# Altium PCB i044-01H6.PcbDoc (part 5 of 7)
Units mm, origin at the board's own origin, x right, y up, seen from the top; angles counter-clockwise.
Board outline 42 x 29.01 mm, 8 copper layers (Top Layer, Mid-Layer 1, Mid-Layer 2, Mid-Layer 3, Mid-Layer 4, Mid-Layer 5, Mid-Layer 6, Bottom Layer), stack 1.474 mm thick; 235 components, 197 nets, 1006 pads, 1183 vias.
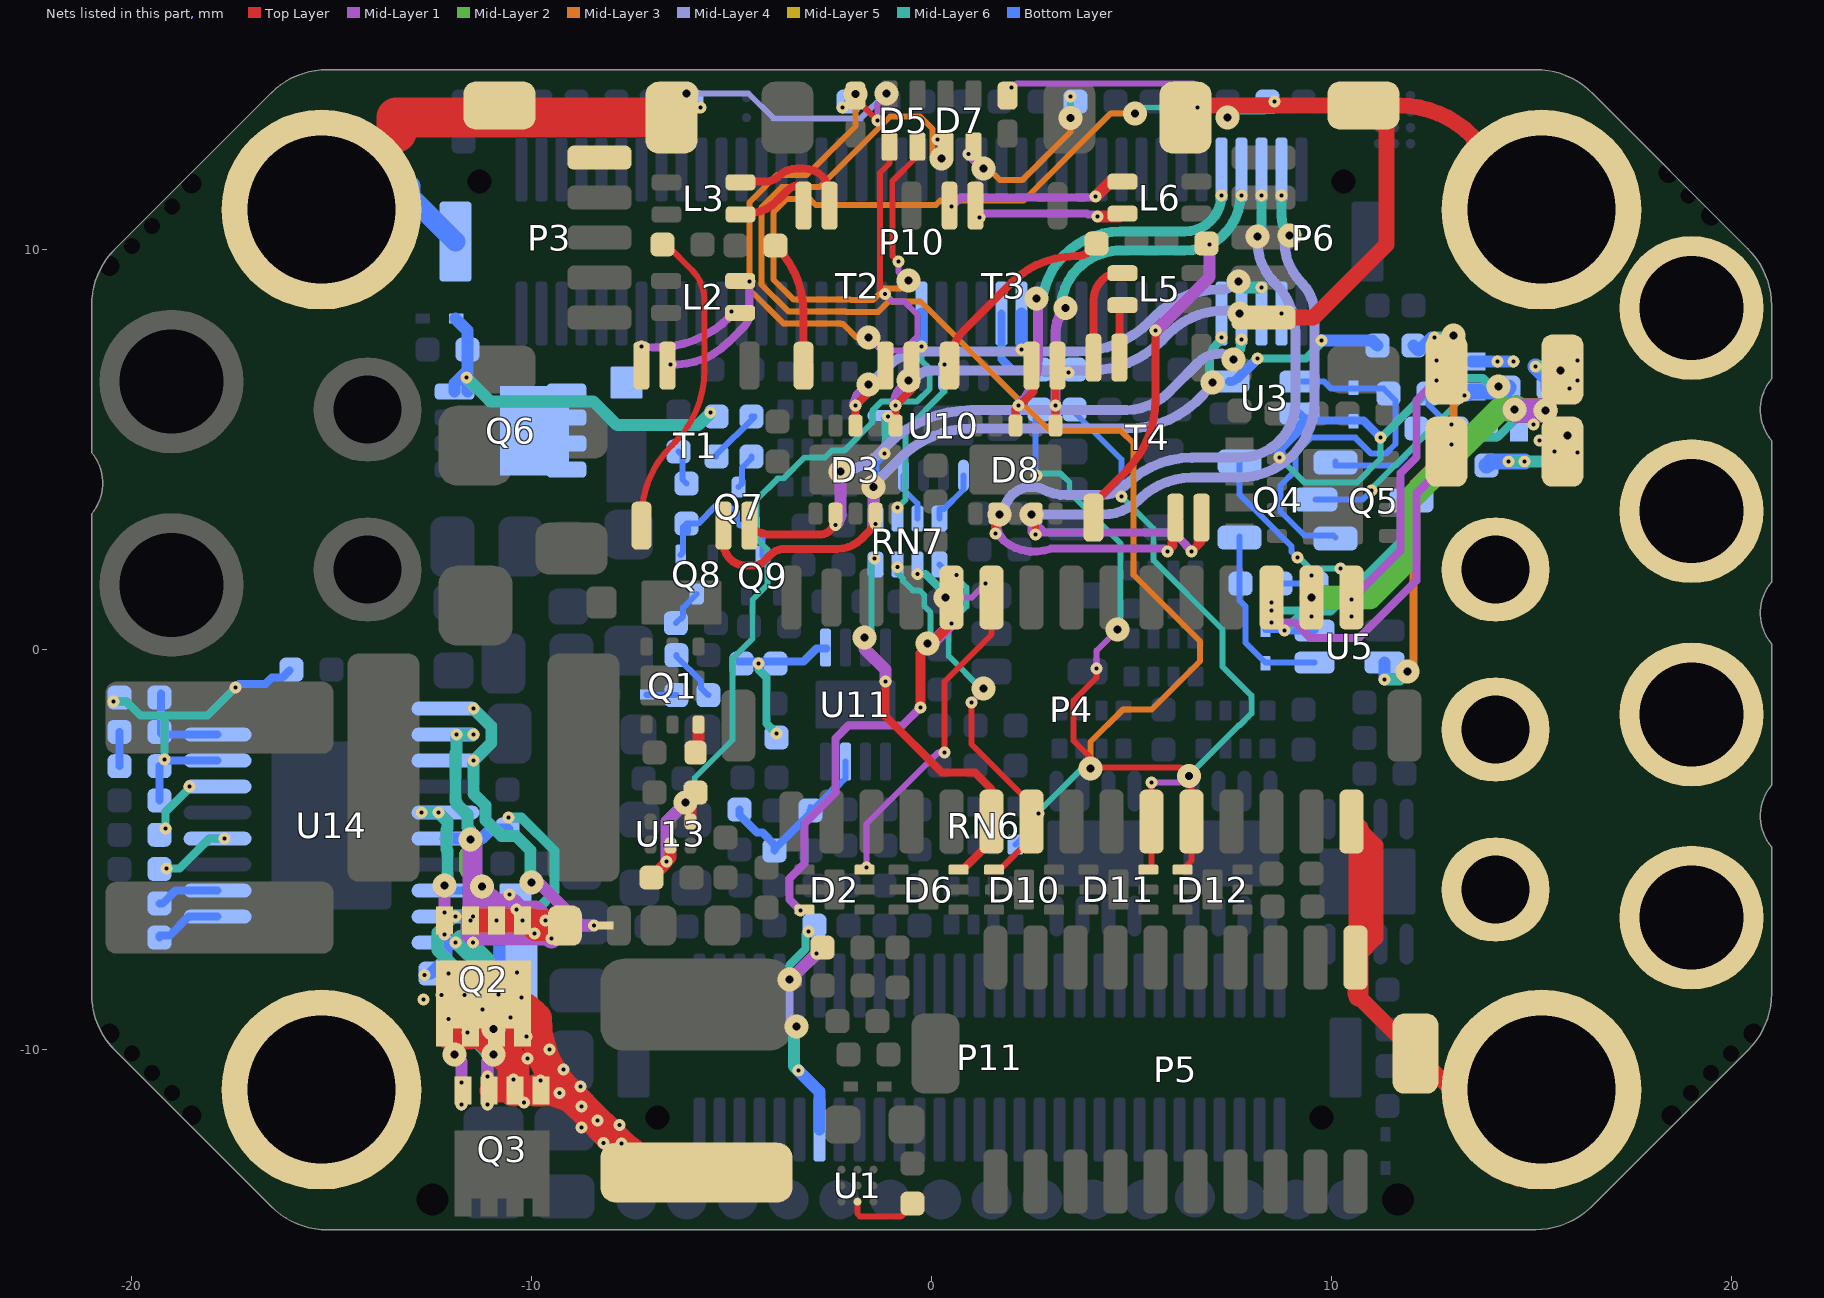
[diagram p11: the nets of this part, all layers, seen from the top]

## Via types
v1: diameter 0.3/0.3 (per signal layer), hole 0.1, Mid-Layer 6 to Bottom Layer, 515 vias
v2: diameter 0.3/0.3 (per signal layer), hole 0.1, Top Layer to Mid-Layer 1, 392 vias
v3: diameter 0.6, hole 0.2, Mid-Layer 1 to Mid-Layer 6, 276 vias

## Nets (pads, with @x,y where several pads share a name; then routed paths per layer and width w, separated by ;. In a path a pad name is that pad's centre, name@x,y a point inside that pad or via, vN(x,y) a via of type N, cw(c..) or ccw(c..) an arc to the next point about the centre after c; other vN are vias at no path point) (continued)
NetC33_1: C33.1 R35.1 R37.2 U11.3 | length 4.6
  Bottom Layer w0.15: C33.1@-3.025,-3.938 C33.1@-3.025,-4.025 C33.1@-3.01,-4.025 ; C33.1@-3.011,-4.026 C33.1@-3.01,-4.025 ; C33.1@-3.005,-4.025 C33.1@-3.01,-4.025 ; -2.433,-3.475 -2.408,-3.475 U11.3@-2.15,-3.217 ; -2.416,-3.488 -2.469,-3.489 C33.1@-3.01,-4.025 ; U11.3@-2.15,-3.192 U11.3@-2.15,-2.8
  Bottom Layer w0.2: R35.1@-4.8,-4 -4.8,-4.134 -4.359,-4.575 -4.226,-4.575 -3.925,-4.876 R37.2@-3.925,-4.989 ; R37.2@-3.925,-5.025 R37.2@-3.925,-4.989 ; R37.2@-3.925,-4.925 R37.2@-3.925,-4.989 ; C33.1@-3.025,-4.025 -3.025,-4.089 R37.2@-3.925,-4.989
NetC34_2: C34.2 R36.1 R38.1 U11.5 | length 4.3
  Mid-Layer 6 w0.2: v1(-4.325,-0.35) -4.325,-0.5 -4.125,-0.7 -4.125,-1.85 v1(-3.875,-2.1)
  Bottom Layer w0.2: R38.1@-4.825,-0.3 -3.2,-0.3 -2.875,0.025 U11.5@-2.627,0.025
NetC40_1: C40.1 U14.5 | length 1.8
  Mid-Layer 6 w0.2: v1(-19.125,-5.475) -18.8,-5.475 -18.05,-4.725 v1(-17.675,-4.725)
NetC41_2: C41.2 U14.2 | length 1.7
  Bottom Layer w0.2: C41.2@-19.3,-7.2 -19.3,-7.143 -19.043,-7.143 -18.575,-6.675 U14.2@-17.85,-6.675
NetC44_1: C44.1 L1.1 Q2.5 Q2.6 Q2.7 Q2.8 Q2.9 Q3.1 Q3.2 Q3.3 U14.20 | length 22.5
  Top Layer w0.6: Q2.5@-12.075,-9.7 Q2.6@-11.525,-9.7 ; Q3.3@-11,-11.025 -10.45,-11.025 Q3.1@-9.9,-11.025 ; Q2.7@-10.875,-9.7 Q2.8@-10.325,-9.7
  Top Layer w0.8: Q3.2@-10.45,-11.025 v2(-10.45,-10.75) -10.45,-10.343 -11.2,-9.593 Q2.9@-11.2,-8.625 cw(c-11.2,-10.333) -9.992,-9.125 -9.891,-9.226 ccw(c-7.351,-9.226) -9.147,-11.023 v2@-8.825,-11.345 ; Q3.1@-9.9,-11.025 -9.8,-11.025 -9.597,-11.025 cw(c-9.597,-12.116) v2@-8.825,-11.345 ; L1.1@-5.875,-13.075 -6.043,-13.075 cw(c-6.043,-10.535) -7.839,-12.331 v2(-8.745,-11.425) v2@-8.825,-11.345
  Mid-Layer 1 w0.3: v2(-11.104,-11.366) v2(-11.104,-10.675) -11.104,-10.279 v3(-10.95,-10.125)
  Mid-Layer 2 w0.3: v3(-10.95,-10.125) v3(-10.95,-9.487)
  Mid-Layer 3 w0.3: v3(-10.95,-10.125) v3(-10.95,-9.487)
  Mid-Layer 4 w0.3: v3(-10.95,-10.125) v3(-10.95,-9.487)
  Mid-Layer 5 w0.3: v3(-10.95,-10.125) v3(-10.95,-9.487)
  Mid-Layer 6 w0.6: -11.72,-7.293 -11.225,-7.788 -11.225,-9.212 ; v3(-10.95,-10.125) v3@-10.95,-10.039 ; -11.225,-9.212 -11.226,-9.214 -11.226,-9.763 v3@-10.95,-10.039 ; -11.225,-9.212 v3(-10.95,-9.487) v3@-10.95,-10.039
  Bottom Layer w0.3: C44.1@-12.525,-8.1 -12.125,-7.7 U14.20@-12.125,-7.325
  other v1: -11.9,-7.325 -11.467,-7.325
  other v2: -7.75,-12.35 -8.197,-12.331 -8.75,-11.941 -7.8,-11.885 -8.35,-11.775 -10.191,-11.325 -9.3,-11.082 -8.775,-10.925 -9.775,-10.775 -9.2,-10.5 -10.1,-10.225 -9.546,-10.001 -10.125,-9.675 -11.6,-9.574 -12.079,-9.23 -10.525,-9.2 -11.225,-9 -12.7,-8.75 -10.251,-8.7 -12.25,-8.635 -11.675,-8.635 -10.826,-8.625 -12.675,-8.133 -11.25,-8.133 -12.075,-8.1 -10.366,-8.075
NetC44_2: C44.2 D19.2 U14.18 | length 4.4
  Bottom Layer w0.2: U14.18@-12.15,-6.025 -11.478,-6.025 -11.05,-6.453 -11.05,-6.912 ; C44.2@-11.6,-8.1 C44.2@-11.525,-8.1 ; D19.2@-10.851,-7.799 -10.55,-8.1 D19.2@-10.4,-8.25
  Bottom Layer w0.3: C44.2@-11.525,-8.1 D19.2@-10.55,-8.1 ; -11.05,-6.912 -10.8,-7.162 D19.2@-10.8,-7.799
NetC45_2: C45.2 U14.7 | length 1.3
  Mid-Layer 6 w0.2: v1(-19.15,-4.475) -19.15,-4.06 -18.55,-3.46 v1(-18.55,-3.425)
NetC47_1: C47.1 R44.1 R45.2 R46.2 U14.8 | length 8.3
  Mid-Layer 6 w0.2: v1(-20.45,-1.3) -20.126,-1.3 -19.776,-1.65 -19.15,-1.65 ; v1(-19.175,-2.75) -19.175,-1.675 -19.15,-1.65 ; v1(-17.4,-0.95) -18.1,-1.65 -19.15,-1.65
  Bottom Layer w0.2: R44.1@-19.3,-3.771 R46.2@-19.3,-2.914 ; R46.2@-19.161,-2.775 U14.8@-17.85,-2.775 ; v1(-17.4,-0.95) -17.311,-0.861 -16.651,-0.861 -16.49,-0.7 -16.225,-0.7 R45.2@-16.05,-0.525
NetC47_2: C47.2 C51.2 U14.9 | length 2.4
  Bottom Layer w0.2: C47.2@-19.258,-1.1 -19.258,-2.1 -19.232,-2.125 U14.9@-17.85,-2.125
NetC49_2: C49.2 D19.1 U14.16 | length 5.7
  Mid-Layer 6 w0.25: v1(-10.575,-4.2) -10.248,-4.2 -9.425,-5.023 -9.425,-6.062 -9.864,-6.5 v1(-10.375,-6.5) -10.547,-6.328 v1(-10.547,-6.125)
  Bottom Layer w0.3: U14.16@-12.15,-4.725 -11.25,-4.725 -11.025,-4.5 C49.2@-10.6,-4.5
NetC51_1: C51.1 R46.1 | length 0.9
  Bottom Layer w0.2: R46.1@-20.3,-2.914 C51.1@-20.3,-2.057
NetD4_2: D4.2 R29.1 | length 8.1
  Top Layer w0.15: D4.2@-1.9,13.85 -1.9,13.745 -1.87,13.745 v2(-1.35,13.225)
  Mid-Layer 1 w0.15: v2(-1.35,13.225) -1.35,13.65 -1.148,13.852 v3@-1.148,13.9
  Mid-Layer 4 w0.15: v3(-6.13,13.905) -4.575,13.905 -3.95,13.28 -1.768,13.28 v3@-1.148,13.9
  Mid-Layer 6 w0.15: v3(-6.13,13.905) v1(-5.775,13.55)
  Bottom Layer w0.15: R29.1@-6,13.7 -6,13.5 -5.825,13.5 v1(-5.775,13.55)
  other v3: -1.123,13.9
NetD5_1: D5.1 R31.2 | length 17.3
  Top Layer w0.15: v2(-1.16,8.885) -1.294,9.019 -1.294,11.916 -1.05,12.16 D5.1@-1.05,12.575
  Mid-Layer 1 w0.15: v3(-1.575,7.8) -1.25,7.475 -0.715,7.475 -0.35,7.84 -0.35,8.367 -0.688,8.705 -0.98,8.705 v2(-1.16,8.885)
  Mid-Layer 3 w0.15: v3@-1.921,13.895 v3(-1.9,13.895) -1.9,13.088 -3.123,11.865 -3.866,11.865 -4.55,11.181 -4.55,9.002 -3.703,8.155 -2.281,8.155 -2.267,8.141 -2.209,8.141 -1.868,7.8 v3(-1.575,7.8)
  Mid-Layer 6 w0.15: v1(-2.225,13.55) -2.225,13.57 v3(-1.9,13.895)
NetD5_2: D5.2 R25.2 | length 21.1
  Top Layer w0.15: v2(-0.825,9.7) -0.97,9.845 -0.97,11.721 -0.35,12.341 D5.2@-0.35,12.575
  Mid-Layer 1 w0.15: v2(-0.825,9.7) -0.825,9.435 v3@-0.59,9.2
  Mid-Layer 3 w0.15: v3@-0.57,9.23 -0.775,9.025 -1.175,9.025 -1.459,8.741 -2.018,8.741 -2.032,8.755 -3.454,8.755 -3.95,9.251 -3.95,10.932 -3.617,11.265 -3.04,11.265 -2.89,11.115 0.108,11.115 0.218,11.225 2.3,11.225 4.485,13.41 v3(5.083,13.41)
  Mid-Layer 6 w0.15: v3(5.083,13.41) 5.224,13.55 v1(6.65,13.55)
  other v3: -0.58,9.23
NetD7_1: D7.1 RN6.1 | length 33.7
  Top Layer w0.15: v2(0.15,12.75) 0.18,12.75 0.205,12.775 0.265,12.715 0.265,12.54 D7.1@0.35,12.54
  Mid-Layer 1 w0.15: v2(0.15,12.75) 0.25,12.65 v3(0.25,12.275)
  Mid-Layer 3 w0.15: v3(0.25,12.275) 0.25,12.108 0.025,12.333 0.025,13.017 -0.283,13.325 -1.037,13.325 -2.797,11.565 -3.742,11.565 -4.25,11.057 -4.25,9.126 -3.579,8.455 -2.156,8.455 -2.142,8.441 -1.335,8.441 -1.071,8.705 -0.627,8.705 -0.276,8.705 2.954,5.475 4.731,5.475 5.05,5.156 5.05,1.867 6.715,0.202 6.715,-0.285 5.5,-1.5 4.783,-1.5 3.975,-2.308 v3(3.975,-2.975)
  Mid-Layer 6 w0.15: v1(2.675,-4.1) 2.675,-4.058 3.758,-2.975 v3(3.975,-2.975)
  Bottom Layer w0.15: RN6.1@2.1,-4.875 2.675,-4.3 v1(2.675,-4.1)
NetD7_2: D7.2 R27.2 | length 4.5
  Top Layer w0.15: D7.2@1.05,12.54 D7.2@1.05,12.575
  Mid-Layer 1 w0.25: v2(0.93,12.395) v3(1.3,12.025)
  Mid-Layer 3 w0.15: v3@1.26,12.24 v3@1.45,12.05 ; v3(1.3,12.025) 1.422,12.025 1.711,11.736 2.267,11.736 3.47,12.938 v3(3.47,13.29)
  Mid-Layer 6 w0.15: v3(3.47,13.29) 3.475,13.295 v1(3.475,13.825)
NetD9_2: D9.2 R22.1 | length 7.1
  Mid-Layer 1 w0.15: v2@2,14.025 2.125,14.15 6.55,14.15 v3(7.4,13.3)
  Mid-Layer 6 w0.15: v3(7.4,13.3) 7.55,13.45 8.325,13.45 v1(8.575,13.7)
  other v2: 2,14.05
NetD15_1: D15.1 Q4.3 R55.1 | length 6
  Mid-Layer 6 w0.15: v1(11,3.975) 11,4.025 v1(13.325,6.35)
  Bottom Layer w0.15: Q4.3@9.6,3.75 10.775,3.75 v1(11,3.975)
  Bottom Layer w0.3: v1(13.325,6.35) 13.4,6.35 D15.1@13.5,6.45
  Bottom Layer w0.4: D15.1@13.5,6.45 14.325,6.45 R55.1@14.425,6.55
NetD16_1: D16.1 Q6.4 R2.2 R58.2 | length 9.3
  Mid-Layer 6 w0.3: v1(-11.625,6.8) -11.033,6.208 -8.459,6.208 -7.867,5.615 -5.835,5.615 v1(-5.525,5.925)
  Bottom Layer w0.3: Q6.4@-11.925,6.45 -11.925,6.65 -11.6,6.975 ; D16.1@-11.9,8.275 -11.6,7.975 R58.2@-11.6,7.5 -11.6,6.975 ; Q6.4@-11.6,6.457 -11.6,6.975
NetD17_1: D17.1 R49.1 | length 0.8
  Bottom Layer w0.15: D17.1@-7.13,-1.12 -7.12,-1.13 -6.39,-1.13 R49.1@-6.38,-1.14
NetD21_1: D21.1 Q6.5 Q6.6 Q6.7 Q6.8 Q6.9
NetD22_1: D22.1 Q5.3 R56.1 | length 2.8
  Bottom Layer w0.15: R56.1@12.875,4.6 13.03,4.6 D22.1@13.962,5.531
  Bottom Layer w0.4: Q5.3@12,3.725 12.062,3.725 12.409,4.072 12.409,4.127 12.464,4.127 12.875,4.538 R56.1@12.875,4.6
NetD23_2: D23.2 Q4.1 R51.2 U5.1 | length 4.6
  Bottom Layer w0.15: Q4.1@7.7,2.825 7.7,1.232 7.849,1.083 7.849,0.176 8.35,-0.325 U5.1@9.575,-0.325
NetD24_2: D24.2 Q5.1 R53.2 U3.1 | length 9.9
  Bottom Layer w0.15: U3.1@9.2,6.7 9.814,6.7 9.989,6.525 10.55,6.525 11.3,6.525 R53.2@11.425,6.4 11.6,6.225 11.6,5.14 11.36,4.9 10.995,4.9 10.595,5.3 9.48,5.3 9.102,4.921 9.102,4.484 8.725,4.107 8.725,3.453 9.325,2.853 10.047,2.853 Q5.1@10.1,2.8
NetL2_3: L2.3 T1.4 | length 2.6
  Mid-Layer 1 w0.2: v2(-7.25,7.575) ccw(c-6.907,10.206) -5.03,8.329 ccw(c-5.101,8.4) -5,8.4 v2(-5,8.45)
NetL2_4: L2.4 T1.5 | length 3.4
  Mid-Layer 1 w0.2: v2@-6.597,7.137 ccw(c-6.421,9.029) -5.077,7.686 -4.691,8.072 ccw(c-5.031,8.412) -4.55,8.412 v2(-4.55,9.2) cw(c-4.61,9.14) v2@-4.525,9.14
  other v2: -6.525,7.125
NetL3_3: L3.3 T2.4 | length 1.9
  Top Layer w0.2: L3.3@-4.775,10.9 -4.635,10.9 ccw(c-4.635,12.01) -3.85,11.225 -3.6,11.475 cw(c-3.338,11.262) T2.4@-3.125,11.525
NetL3_4: L3.4 T2.5 | length 3
  Top Layer w0.2: L3.4@-4.775,11.7 -4.162,11.7 ccw(c-4.162,12.212) -3.8,11.85 cw(c-3.378,11.428) -3.378,12.025 -3.188,12.025 cw(c-3.188,11.387) -2.55,11.387 T2.5@-2.55,11.1
NetL5_3: L5.3 T4.4 | length 2.6
  Top Layer w0.2: T4.4@4.05,7.3 4.05,8.725 cw(c4.775,8.725) L5.3@4.775,9.45
NetL5_4: L5.4 T4.5 | length 1.4
  Top Layer w0.2: T4.5@4.7,7.3 4.7,8.65 L5.4@4.775,8.65
NetL6_3: L6.3 T3.4 | length 4.5
  Top Layer w0.3: v2(4.1,11.325) 4.475,11.7 L6.3@4.775,11.7
  Mid-Layer 1 w0.2: v2(0.5,11.075) 0.725,11.3 4.075,11.3 v2(4.1,11.325)
NetL6_4: L6.4 T3.5 | length 3.6
  Top Layer w0.3: v2(4.15,10.825) L6.4@4.7,10.825
  Mid-Layer 1 w0.2: v2(1.2,10.8) 1.3,10.9 3.889,10.9 3.914,10.875 4.15,10.875 v2(4.15,10.825)
NetNT1_1: NT1.1 U14.11 U14.13 | length 7.6
  Mid-Layer 1 w0.3: v3(-10,-5.823) -9.824,-5.823 -8.747,-6.9 v2@-8.5,-6.9
  Mid-Layer 6 w0.3: v1(-11.45,-1.475) -11,-1.925 -11,-2.325 v1(-11.45,-2.775) -11.45,-3.599 -11.156,-3.893 -11.156,-4.255 -10.747,-4.664 -10.385,-4.664 -10.03,-5.019 -10.03,-5.334 -10.025,-5.339 -10.025,-5.875 -10,-5.85 v3(-10,-5.823)
  other v2: -8.442,-6.899
NetQ1_3: Q1.3 R42.2 | length 0.7
  Top Layer w0.3: R42.2@-5.9,-2.575 -5.825,-2.5 Q1.3@-5.825,-1.875
NetQ2_1: Q2.1 Q2.2 Q2.3 R40.2 U14.12 | length 24.1
  Top Layer w0.6: Q2.3@-11.425,-6.775 v2(-10.875,-6.775) v2(-10.225,-6.775) -9.975,-6.775 -9.85,-6.9
  Top Layer w0.8: -9.85,-6.9 R40.2@-9.25,-6.9
  Mid-Layer 1 w0.3: v3@-11.237,-6.012 v3(-11.237,-5.924)
  Mid-Layer 1 w0.5: v3(-11.526,-4.75) -11.476,-4.8 -11.476,-5.773 -11.237,-6.012 -10.898,-6.351 -10.463,-6.351 -10.29,-6.523 -9.902,-6.523 v2(-9.65,-6.775) ; -11.305,-6.377 -11.476,-6.547 ; v2(-11.525,-6.775) -11.525,-7.097 -11.475,-7.147 v2@-9.878,-7.147 ; v2(-11.525,-6.775) -11.525,-6.597 -11.476,-6.547 ; v2(-11.525,-6.775) v2(-10.875,-6.775) ; v2(-11.525,-6.775) -11.476,-6.726 -11.476,-6.547 ; -11.476,-6.547 -11.476,-5.78 -10.875,-6.38 v2(-10.875,-6.775) ; v2(-10.875,-6.775) v2(-10.225,-6.775) ; v2(-10.225,-6.775) v2(-9.65,-6.775) ; v2(-10.225,-6.775) -9.925,-7.075 v2(-9.925,-7.1) v2@-9.878,-7.147 ; v2@-9.878,-7.147 -9.579,-7.147 v2@-9.577,-7.149 ; v2@-9.878,-7.147 -9.876,-7.149 v2@-9.577,-7.149 ; v2(-9.65,-6.775) -9.5,-6.925 v2(-9.5,-7.226) v2@-9.577,-7.149
  Mid-Layer 2 w0.3: v3@-11.531,-4.75 -11.531,-4.995 -11.65,-5.114 -11.65,-5.525 v3@-11.251,-5.924
  Mid-Layer 3 w0.3: v3@-11.531,-4.75 -11.531,-4.995 -11.65,-5.114 -11.65,-5.525 v3@-11.251,-5.924
  Mid-Layer 4 w0.3: v3@-11.531,-4.75 -11.531,-4.995 -11.65,-5.114 -11.65,-5.525 v3@-11.251,-5.924
  Mid-Layer 5 w0.3: v3@-11.531,-4.75 -11.531,-4.995 -11.65,-5.114 -11.65,-5.525 v3@-11.251,-5.924
  Mid-Layer 6 w0.3: v1(-11.45,-2.125) v1(-11.875,-2.125) -11.875,-2.564 -11.9,-2.589 -11.9,-3.785 -11.875,-3.81 -11.875,-3.857 -11.606,-4.126 -11.606,-4.442 -11.531,-4.517 -11.531,-4.995 -11.65,-5.114 -11.65,-5.525 -11.251,-5.924 v3(-11.237,-5.924)
NetQ2_4: Q2.4 U14.15 | length 3.7
  Mid-Layer 1 w0.3: v2(-12.18,-7.125) -12.18,-6.58 v2(-12.175,-6.575) v3(-12.176,-5.9)
  Mid-Layer 6 w0.3: v1(-12.75,-4.075) v1(-12.325,-4.075) -12.1,-4.3 -12.1,-4.476 -12.126,-4.502 -12.126,-4.999 -12.1,-5.024 v3@-12.1,-5.9 ; v3(-12.176,-5.9) v3@-12.1,-5.9
NetQ3_4: Q3.4 U14.19 | length 5.6
  Mid-Layer 1 w0.3: v3(-11.925,-10.125) -11.75,-10.3 v2(-11.75,-10.825) -11.75,-11.362 v2(-11.754,-11.366)
  Mid-Layer 6 w0.3: v3@-11.826,-10.125 -11.826,-8.035 -12.35,-7.511 -12.35,-7.075 -11.95,-6.675 v1(-11.9,-6.675) v1@-11.5,-6.675
  other v1: -11.467,-6.675
NetQ4_2: Q4.2 R50.1 | length 4.7
  Mid-Layer 6 w0.15: v1(9.15,2.3) 9.191,2.3 9.466,2.025 v1(10.225,2.025)
  Bottom Layer w0.15: Q4.2@7.7,4.7 7.7,3.88 8.999,2.581 8.999,2.451 v1(9.15,2.3) ; v1(10.225,2.025) 10.25,2.025 R50.1@10.625,1.65
NetQ5_2: Q5.2 R52.1 | length 2.7
  Bottom Layer w0.15: Q5.2@10.1,4.7 10.1,4.6 11.605,4.6 12.125,5.12 R52.1@12.125,5.525
NetQ7_1: Q7.1 Q8.1 Q9.3 R60.1 | length 4.1
  Bottom Layer w0.15: Q8.1@-6.27,2.37 -6.21,2.43 -6.21,3.065 R60.1@-6.125,3.15 ; R60.1@-6.085,2.924 -6.085,3.11 R60.1@-6.125,3.15 ; Q9.3@-4.225,2.34 -4.225,2.76 -4.425,2.96 Q7.1@-4.425,3.085 -4.442,3.102 -4.777,3.102 -4.865,3.19 -4.865,3.436 -4.935,3.505 -5.179,3.605 -5.378,3.605 -5.834,3.15 R60.1@-6.125,3.15
NetQ7_3: Q7.3 R61.1 | length 0.9
  Bottom Layer w0.15: Q7.3@-4.825,4.065 -4.734,4.156 -4.734,4.55 -4.5,4.784 R61.1@-4.5,4.825
NetQ8_3: Q8.3 R62.1 | length 0.9
  Bottom Layer w0.15: R62.1@-6.39,0.66 -6.211,0.839 -6.211,1.049 Q8.3@-5.87,1.39
NetR1_1: R1.1 R49.2 | length 1.3
  Bottom Layer w0.15: R49.2@-6.38,-0.14 -6.38,-0.17 -5.759,-0.792 -5.759,-0.961 R1.1@-5.58,-1.14
NetR2_1: R2.1 R61.2 | length 1.5
  Bottom Layer w0.15: R2.1@-5.391,4.825 -5.391,4.858 -4.424,5.825 R61.2@-4.5,5.825
NetR9_2: R9.2 T1.3 | length 8
  Top Layer w0.15: T1.3@-7.25,3.1 T1.3@-7.25,3.287 ; T1.3@-7.25,3.325 T1.3@-7.25,3.287 ; R9.2@-6.645,10.125 R9.2@-6.725,10.125 cw(c-6.725,9.886) -6.556,10.055 -5.988,9.487 cw(c-6.742,8.732) -5.675,8.732 -5.675,6.988 cw(c-8.24,6.988) -6.426,5.174 -6.499,5.101 ccw(c-4.685,3.287) T1.3@-7.25,3.287
NetR10_1: R10.1 T2.3 | length 3.2
  Top Layer w0.2: R10.1@-3.9,10.1 cw(c-5.59,8.41) -3.2,8.41 T2.3@-3.2,7.1
NetR14_1: R14.1 T4.3 | length 7.9
  Top Layer w0.2: T4.3@4.05,3.3 cw(c4.895,3.3) 4.297,3.897 4.856,4.456 ccw(c3.06,6.252) 5.6,6.252 v2(5.6,7.98)
  Mid-Layer 1 w0.3: v2(5.6,7.98) 5.618,7.98 6.95,9.312 v2(6.95,10.125)
NetR15_2: R15.2 T3.3 | length 5.1
  Top Layer w0.2: T3.3@0.45,7.1 cw(c1.717,7.1) 0.821,7.996 1.998,9.173 cw(c3.6,7.57) 3.6,9.836 ccw(c3.6,10.467) 4.046,10.021 R15.2@4.15,10.125
NetR17_2: R17.2 R56.2 | length 3.1
  Mid-Layer 6 w0.3: v1(14.425,4.7) v1(14.825,4.7) 15.8,4.7 15.9,4.8 v3@15.9,5.225 ; v3(15.9,5.35) v3@15.9,5.225 ; v3@15.925,5.2 v3@15.9,5.225
  Bottom Layer w0.4: R56.2@13.875,4.6 13.975,4.7 v1(14.425,4.7) v1(14.825,4.7)
  other v2: 16.15,4.925 15.575,4.95
NetR18_2: R18.2 R55.2 | length 2.4
  Mid-Layer 6 w0.3: v1(15.1,7.075) 15.625,7.075 v3(15.725,6.975) 15.725,6.75 v1(15.95,6.525)
  Bottom Layer w0.4: v1(15.1,7.075) 15.425,6.75 R55.2@15.425,6.55 15.925,6.55 v1(15.95,6.525)
  other v2: 16.15,6.725 16.15,7.225
NetR19_1: R19.1 U5.4 | length 11.2
  Mid-Layer 3 w0.2: v3(11.9,-0.55) 12.055,-0.395 12.055,4.167 13.05,5.161 v3(13.05,7.85)
  Mid-Layer 6 w0.3: v1(11.325,-0.75) 11.7,-0.75 v3(11.9,-0.55) ; v1(12.575,7.8) 13,7.8 v3(13.05,7.85)
  Bottom Layer w0.3: v1(11.325,-0.75) U5.4@11.325,-0.325 ; R19.1@12.05,7.6 12.175,7.475 12.5,7.8 v1(12.575,7.8)
NetR39_1: R39.1 U3.4 | length 4.2
  Mid-Layer 6 w0.2: v1(8.15,7.275) 9.366,7.275 9.75,7.659 v1(9.75,7.725)
  Bottom Layer w0.22: U3.4@7.45,6.7 ccw(c7.45,7.002) U3.4@7.663,6.788
  Bottom Layer w0.25: U3.4@7.663,6.788 v1(8.15,7.275)
  Bottom Layer w0.3: v1(9.75,7.725) 11.025,7.725 R39.1@11.15,7.6
NetR42_1: R42.1 U13.4 | length 0.8
  Top Layer w0.3: U13.4@-6.025,-4.3 -6.025,-3.7 R42.1@-5.9,-3.575
NetR43_1: R43.1 U14.3 | length 1.6
  Bottom Layer w0.2: R43.1@-19.3,-6.343 -19.221,-6.343 -18.903,-6.025 U14.3@-17.85,-6.025
NetR48_1: R48.1 U1.C2 | length 1.9
  Top Layer w0.15: U1.C2@-1.85,-13.8 -1.85,-14.102 -1.778,-14.174 -0.774,-14.174 R48.1@-0.45,-13.85
NetR50_2: R50.2 R51.1 | length 1
  Bottom Layer w0.15: R51.1@8.725,1.65 R50.2@9.625,1.65 9.675,1.65 R50.2@9.7,1.675
NetR52_2: R52.2 R53.1 | length 1.4
  Bottom Layer w0.15: R53.1@12.425,6.4 12.425,6.125 13.025,5.525 R52.2@13.125,5.525 R52.2@13.33,5.525
NetR59_1: R59.1 R60.2 | length 0.9
  Bottom Layer w0.15: R59.1@-6.325,4.95 -6.225,4.85 -6.225,4.25 R60.2@-6.125,4.15
NetRN7_2: RN7.2 U10.3 | length 1.4
  Bottom Layer w0.15: RN7.2@0.2,3.275 0.2,3.51 0.307,3.51 0.8,4.003 U10.3@0.8,4.35
NetRN7_4: RN7.4 U10.6 | length 1.2
  Bottom Layer w0.15: U10.6@-0.7,4.35 -0.7,4.003 -0.35,3.653 RN7.4@-0.35,3.275
NetRN7_6: RN7.6 U10.11 | length 4.1
  Mid-Layer 6 w0.15: v1(-0.85,3.55) -0.65,3.75 -0.65,5.488 0.32,6.458 v1(0.32,7.13)
NetRN7_8: RN7.8 U10.8 | length 2.7
  Mid-Layer 6 w0.2: v1(-1.17,4.9) -1.155,4.915 -1.155,5.765 v1(-1.09,5.83)
  Bottom Layer w0.2: RN7.8@-1.4,3.275 -1.4,4.67 v1(-1.17,4.9)
OUT1: D10.1 P4.18 RN7.1 | length 9.9
  Top Layer w0.15: v2(1,-1.32) 1,-2.364 2.5,-3.864 P4.18@2.5,-4.3 2.5,-4.701 1.701,-5.5 D10.1@1.562,-5.5
  Mid-Layer 1 w0.15: v2(1,-1.32) 1.3,-1.02 v3(1.3,-0.97)
  Mid-Layer 6 w0.15: v1@0.678,1.9 0.648,1.87 v1(0.63,1.87) 0.63,1.808 0.625,1.803 0.875,1.553 0.875,1.083 0.425,0.633 0.425,-0.155 v3@1.26,-0.99
  Bottom Layer w0.15: RN7.1@0.2,2.125 0.375,1.95 0.425,2 0.555,1.87 v1(0.63,1.87)
OUT2: D2.6 P4.19 RN7.3 | length 10.4
  Top Layer w0.15: D2.6@-1.736,-5.5 D2.6@-1.675,-5.5 D2.6@-1.65,-5.5 ; v2(0.325,-2.575) 0.325,-0.8 1.5,0.375 P4.19@1.5,1.3
  Mid-Layer 1 w0.15: v2(-1.625,-5.45) -1.625,-4.358 0.158,-2.575 v2(0.325,-2.575) ; v3(0.35,1.3) 1,1.3 v2(1.35,1.65)
  Mid-Layer 6 w0.15: v3(0.35,1.3) v3@0.35,1.39
  Mid-Layer 6 w0.2: v1(-0.35,1.89) -0.15,1.89 v3@0.35,1.39
OUT3: D6.6 P4.20 RN7.7 | length 10.1
  Top Layer w0.2: v2(-1.15,-0.8) -1.15,-1.666 0.259,-3.075 1.084,-3.075 1.5,-3.491 P4.20@1.5,-4.3 1.5,-4.785 0.785,-5.5 D6.6@0.706,-5.5
  Mid-Layer 1 w0.3: v3(-1.675,0.3) -1.675,0.026 -1.15,-0.499 v2(-1.15,-0.8)
  Mid-Layer 6 w0.15: v3(-1.675,0.3) -1.5,0.475 -1.5,2.2 v1(-1.425,2.275)
OUT4: D2.3 P4.21 RN7.5 | length 13.7
  Top Layer w0.2: v2(-3.275,-6.525) -3.2,-6.525 D2.3@-3.175,-6.5
  Top Layer w0.25: v2(-0.275,-1.444) -0.275,-0.1 0.5,0.675 P4.21@0.5,1.3
  Mid-Layer 1 w0.2: v2(-3.275,-6.525) -3.55,-6.25 -3.55,-5.722 -3.177,-5.349 -3.177,-4.354 -2.4,-3.577 -2.4,-2.222 -2.078,-1.9 -0.731,-1.9 v2(-0.275,-1.444)
  Mid-Layer 1 w0.3: v3(-0.1,0.15) 0,0.15 v2(0.5,0.65)
  Mid-Layer 6 w0.15: v1(-0.85,2.065) -0.85,1.917 -0.707,1.775 -0.707,1.717 -0.472,1.482 -0.3,1.482 -0.175,1.357 -0.175,1.083 -0.025,0.933 -0.025,0.225 v3(-0.1,0.15)
PE: C11.1 H6.1 M2.1 P6.5 P6.S1 pad.8@19,8.54 | length 15
  Top Layer w0.4: C11.1@6.5,13.625 ccw(c6.56,13.685) 6.56,13.6 P6.S1@10.8,13.6 ; P6.5@8.3,8.3 9.541,8.3 11.375,10.134 11.375,13.025 P6.S1@10.8,13.6 ; M2.1@13.575,12.66 ccw(c13.298,12.66) 13.494,12.856 ccw(c11.698,11.06) 11.698,13.6 P6.S1@10.8,13.6
PE1: C3.1 M4.1 P3.5 P3.S2 P10.S1 | length 11.6
  Top Layer w1: -13.372,12.925 -13.372,13.3 C3.1@-6.5,13.3
  Bottom Layer w0.5: M4.1@-15.25,11 -13.624,11 -13.028,11.595 -13.028,11.328 P10.S1@-11.9,10.2
PE2: M3.1
PE3: M1.1 P4.2 P5.20 P5.S2 | length 24.1
  Top Layer w0.4: P4.2@10.5,-4.3 11.096,-4.896 11.096,-7.204 10.675,-7.625 P5.20@10.6,-7.7 10.6,-8.6 10.675,-8.675 P5.S2@12.1,-10.1 13.028,-11.028 13.028,-11.595 13.624,-11 M1.1@15.25,-11 ; M1.1@14.655,-11.595 13.624,-12.626 M1.1@15.25,-11 ; M1.1@14.655,-11.595 M1.1@15.25,-11 ; M1.1@14.655,-11.595 14.655,-13.222 15.25,-12.626 M1.1@15.25,-11
  Top Layer w0.5: 10.675,-8.675 10.675,-7.625 P4.2@10.675,-4.475
PH_A: H3.1 P7.1
PH_B: H4.1 P8.1
PH_C: H5.1 P9.1
PHY0_RX_N: D3.1 P10.77 T2.1 | length 12.8
  Top Layer w0.2: D3.1@-0.9,5.6 v2(-0.9,6.1) -0.5,6.5 T2.1@-0.5,7.1
  Mid-Layer 1 w0.2: v3@-0.71,6.559 -0.65,6.619 -0.606,6.575 -0.54,6.641 -0.549,6.65 v3@-0.63,6.65
  Mid-Layer 1 w0.3: v2(-0.9,6.1) cw(c-0.251,6.1) v3@-0.71,6.559
  Mid-Layer 4 w0.25: v3(7.7,8.4) ccw(c7.504,8.204) 7.504,8.481 7.333,8.481 ccw(c7.333,6.49) 5.925,7.898 5.746,7.719 cw(c3.95,9.515) 3.95,6.975 -0.019,6.975 ccw(c-0.019,6.48) -0.369,6.83 -0.492,6.707 cw(c-0.63,6.846) -0.63,6.65 -0.549,6.65 -0.54,6.641 v3@-0.549,6.632 ; v3@-0.549,6.632 cw(c-0.65,7.027) -0.65,6.619 -0.606,6.575 v3@-0.549,6.632
  Mid-Layer 6 w0.3: v3(7.7,8.4) v1(8.75,8.4)
  other v3: -0.575,6.73
PHY0_RX_P: D3.3 P10.75 T2.2 | length 13.1
  Top Layer w0.2: D3.3@-1.9,5.6 v2(-1.9,6.1) -1.15,6.85 T2.2@-1.15,7.1
  Mid-Layer 1 w0.2: -1.776,6.399 -1.58,6.595 v3(-1.58,6.63)
  Mid-Layer 1 w0.3: v2(-1.9,6.1) cw(c-1.478,6.1) -1.776,6.399
  Mid-Layer 4 w0.25: v3(-1.58,6.63) -1.545,6.63 -1.096,7.079 cw(c-0.2,6.183) -0.2,7.45 3.648,7.45 ccw(c3.648,9.99) 5.444,8.194 5.584,8.334 cw(c7.192,6.725) 7.192,9 ccw(c7.192,9.683) v3(7.675,9.2)
  Mid-Layer 6 w0.3: v3(7.675,9.2) 7.7,9.2 7.85,9.05 v1(8.25,9.05)
PHY0_TX_N: D3.7 P10.73 T1.1 | length 15.7
  Top Layer w0.2: T1.1@-4.55,3.1 ccw(c-4.007,3.643) -4.007,2.875 -2.81,2.875 ccw(c-2.81,3.285) D3.7@-2.4,3.285 ; D3.7@-2.4,3.255 D3.7@-2.4,3.285 ; D3.7@-2.4,3.425 D3.7@-2.4,3.4 D3.7@-2.4,3.285
  Mid-Layer 1 w0.3: v2(-2.4,3.12) ccw(c-2.702,3.422) -2.275,3.422 v3(-2.275,4.45)
  Mid-Layer 4 w0.25: v3@-2.172,4.553 v3(-2.275,4.45) ccw(c-2.436,6.015) -1.32,4.905 -1.119,5.106 cw(c1.002,2.985) 1.002,5.985 4.874,5.985 ccw(c4.829,7.579) 6.05,6.554 6.679,7.182 cw(c7.204,6.657) 7.712,7.2 v3@7.687,7.2
  Mid-Layer 6 w0.25: v3(7.55,7.25) ccw(c7.067,7.733) 7.75,7.733 v1(7.75,7.75)
PHY0_TX_P: D3.9 P10.71 T1.2 | length 17.3
  Top Layer w0.2: T1.2@-5.2,3.1 -5.2,2.665 ccw(c-4.635,2.665) -4.635,2.1 -4.447,2.1 ccw(c-4.447,2.456) -4.196,2.204 -4.036,2.364 cw(c-3.66,1.989) -3.66,2.52 -2.348,2.52 ccw(c-2.348,3.359) -1.754,2.766 -1.598,2.922 ccw(c-2.076,3.4) D3.9@-1.4,3.4
  Mid-Layer 1 w0.2: v3@-1.55,4.1 -1.51,4.06 v3(-1.45,4.06) -1.45,4.1 -1.4,4.15 v3@-1.425,4.175
  Mid-Layer 1 w0.3: v3(-1.45,4.06) -1.45,3.261 ccw(c-1.279,3.261) v2(-1.4,3.14)
  Mid-Layer 4 w0.25: v3(-1.45,4.06) -1.45,4.1 -1.4,4.15 -1.45,4.2 ccw(c-1.45,4.381) -1.322,4.253 -0.794,4.781 cw(c1.002,2.985) 1.002,5.525 4.887,5.525 ccw(c4.887,8.09) v3@7.109,6.808
  Mid-Layer 6 w0.22: v3@7.05,6.7 cw(c7.291,6.941) 6.95,6.941 6.95,7.18 cw(c7.629,7.18) 7.149,7.66 7.171,7.683 v1(7.25,7.8)
  Mid-Layer 6 w0.25: v3@7.05,6.7 v3@7.15,6.8
  other v3: 7.025,6.675
PHY1_RX_N: D8.9 P10.78 T4.1 | length 20.9
  Top Layer w0.2: v2@2.6,2.9 D8.9@2.6,3.4 ; v2(6.5,2.45) 6.75,2.7 T4.1@6.75,3.3 ; 6.65,2.63 T4.1@6.65,3.23
  Mid-Layer 1 w0.2: v3(2.5,3.375) 2.5,2.975 ccw(c2.6,2.975) v2(2.6,2.875) 2.671,2.875 2.721,2.925 2.825,2.925 ; v3@2.525,3.225 2.825,2.925 ; v2(6.5,2.45) 6.517,2.45 6.35,2.617 6.35,2.636 6.086,2.9 6.016,2.9 5.991,2.925 2.825,2.925
  Mid-Layer 4 w0.25: v3(2.5,3.375) 4.278,3.375 ccw(c4.278,4.679) 5.2,3.757 cw(c6.511,2.446) 6.511,4.3 7.675,4.3 ccw(c7.675,6.2) 9.575,6.2 9.575,8.39 ccw(c8.465,8.39) 9.25,9.175 cw(c10.276,10.201) v3@8.825,10.201
  Mid-Layer 6 w0.25: v1(8.75,11.35) 8.75,10.833 ccw(c9.433,10.833) v3(8.95,10.35)
PHY1_RX_P: D8.7 P10.76 T4.2 | length 22.2
  Top Layer w0.2: v2(1.6,2.9) D8.7@1.6,3.4 ; v2(5.9,2.45) 6.05,2.6 6.05,3.25 T4.2@6.1,3.3 ; v2@6,2.56 T4.2@6,3.16
  Mid-Layer 1 w0.2: v2(1.6,2.9) 1.6,3.315 cw(c1.685,3.315) v3@1.625,3.375 ; v3@1.6,3.35 cw(c1.7,3.35) 1.7,3.45 v3(1.7,3.375) ; v3@1.65,3.35 1.65,3.077 ccw(c2.077,3.077) 1.775,2.775 ; v2@1.668,2.861 ccw(c2.569,3.642) 2.985,2.525 ccw(c2.569,3.642) 2.998,2.53 ; 3,2.525 5.769,2.525 cw(c5.769,2.269) v2@5.833,2.517 ; v2@5.825,2.525 v2@5.833,2.517 ; v2(5.9,2.45) v2@5.833,2.517 ; v2@5.95,2.45 ccw(c5.769,2.269) v2@5.833,2.517
  Mid-Layer 4 w0.25: v3(1.7,3.375) v3@1.7,3.461 ; v3@1.804,3.371 cw(c2.504,3.371) 2.743,4.029 ccw(c3.388,5.195) 3.401,3.863 4.252,3.863 ccw(c4.252,4.713) 4.853,4.112 cw(c6.515,2.45) 6.515,4.8 ; 6.511,4.796 6.515,4.8 ; v3(8.15,10.325) 8.15,10.201 ccw(c9.601,10.201) 8.575,9.175 cw(c7.308,7.908) 9.1,7.908 9.1,6.2 cw(c7.7,6.2) 7.7,4.8 6.515,4.8
  Mid-Layer 6 w0.25: v3(8.15,10.325) ccw(c7.909,10.566) 8.25,10.566 v1(8.25,11.35)
PHY1_TX_N: D8.1 P10.74 T3.1 | length 10.3
  Top Layer w0.2: D8.1@3.1,5.6 v2(3.1,6.1) 3.1,7 T3.1@3.2,7.1
  Mid-Layer 1 w0.25: v2(3.1,6.1) 3.1,7.936 cw(c3.954,7.936) v3(3.35,8.54)
  Mid-Layer 6 w0.25: v3@3.225,8.475 cw(c4.725,8.475) 4.725,9.975 ; 4.625,9.975 6.325,9.975 ccw(c6.325,11.375) v1@7.725,11.375
  other v1: 7.75,11.35
PHY1_TX_P: D8.3 P10.72 T3.2 | length 10.4
  Top Layer w0.2: D8.3@2.1,5.6 2.1,6 2.55,6.45 T3.2@2.55,7.1
  Mid-Layer 1 w0.25: v2(2.175,6.1) 2.187,6.112 ccw(c1.052,7.247) 2.657,7.247 v3@2.657,8.775
  Mid-Layer 6 w0.25: v3@2.775,8.819 cw(c4.725,8.475) 4.725,10.455 ; 4.725,10.45 6.325,10.45 ccw(c6.325,11.375) v1@7.25,11.375 ; v1@7.25,11.275 v1(7.25,11.35)
  other v3: 2.625,8.775
PWM_BRAKE: P10.41 R41.2 U13.2 | length 18.7
  Top Layer w0.3: R41.2@-7,-5.7 -6.625,-5.325 v2(-6.625,-5.3) -6.525,-5.2 U13.2@-6.525,-4.9
  Mid-Layer 1 w0.3: v2(-6.625,-5.3) -6.625,-4.3 v3(-6.15,-3.825)
  Mid-Layer 6 w0.15: v3@-6.094,-3.719 -5.925,-3.55 -5.925,-3.208 -4.975,-2.258 -4.975,-0.225 -4.475,0.275 -4.475,1.242 -4.1,1.617 -4.1,2.5 -4.375,2.775 -4.375,3.217 -4.375,3.745 -3.845,4.275 -3.708,4.275 -3.179,4.804 -2.664,4.804 -2.492,4.975 -2.185,4.975 -1.48,5.68 -1.48,5.97 -1.245,6.205 -0.358,6.205 -0.05,6.513 -0.05,6.952 -0.055,6.957 -0.055,7.03 -0.25,7.225 v1(-0.25,7.58)
  Bottom Layer w0.3: v1(-0.25,7.58) P10.41@-0.25,8.4
STO1_IN: P4.1 R18.1 | length 7.3
  Mid-Layer 1 w0.2: v2(10.5,1.25) 11.725,2.475 11.725,4.41 12.125,4.81 12.125,6.225 v2(12.625,6.725) v2(12.625,7.225)
  Mid-Layer 1 w0.3: v2(10.5,0.825) v2(10.5,1.25)
STO2_IN: P4.5 R17.1 | length 9.1
  Mid-Layer 1 w0.2: v2(8.5,1.175) v2(8.5,0.675) 9.084,0.675 9.471,0.288 10.679,0.288 12.124,1.733 12.124,3.904 13,4.78 v2(13,5.125) v2(13,5.625)
STO_RET: D15.2 D22.2 D23.1 D24.1 P4.3 U3.2 U5.2 | length 34.2
  Mid-Layer 1 w0.3: v2(9.5,0.825) v3(9.5,1.3) v2(9.5,1.85)
  Mid-Layer 1 w0.6: v3(14.575,6) 14.602,5.973 v3(15.354,5.973)
  Mid-Layer 2 w0.6: v3(9.5,1.3) 10.95,1.3 11.924,2.274 11.924,3.728 14.196,6 v3(14.575,6) v3@14.625,6.05
  Mid-Layer 3 w0.6: v3(14.575,6) 14.602,5.973 v3(15.354,5.973)
  Mid-Layer 6 w0.15: v1(8.7,4.8) 9.326,4.174 10.631,4.174 11.225,4.768 11.225,5.275 v1(11.225,5.3)
  Mid-Layer 6 w0.2: v1(8.5,0.975) 9.275,0.975 9.3,0.95 ; v1(8.825,0.475) 9.3,0.95 ; v1@11.225,5.275 12.74,6.79 13.785,6.79 v3(14.575,6) 14.575,5.733 14.16,5.318 13.459,5.318 12.161,4.02 12.128,4.02 11.8,3.692 11.8,2.775 9.975,0.95 9.3,0.95
  Bottom Layer w0.15: v1(8.5,0.975) ccw(c8.862,0.613) 8.35,0.613 D23.1@8.35,0.495 8.777,0.495 cw(c8.777,0.427) v1(8.825,0.475)
  Bottom Layer w0.2: v1(8.825,0.475) U5.2@9.575,0.475 ; U3.2@9.2,5.9 9.375,5.725 10.8,5.725 v1(11.225,5.3)
  Bottom Layer w0.3: v1(8.7,4.8) 8.7,5.05 U3.2@9.375,5.725 ; D15.2@13.5,7.2 v1(14.15,7.2) v1(14.55,7.2)
  other v1: 15.2,5.225 15.05,5.625
  other v3: 14.175,6.575
TEMP_MOTOR: C32.2 P11.13 R6.1 | length 6.5
  Mid-Layer 1 w0.3: v3@-3.392,-8.317 -3.392,-8.117 v2(-2.875,-7.6)
  Mid-Layer 4 w0.2: v3(-3.55,-8.25) -3.55,-9.25 v3(-3.375,-9.425)
  Mid-Layer 6 w0.2: v3(-3.55,-8.25) -3.55,-7.882 -3.149,-7.481 -3.149,-7.124 v1(-3.075,-7.05)
  Mid-Layer 6 w0.3: v3@-3.35,-9.45 v3(-3.375,-9.425) -3.437,-9.487 -3.437,-10.413 v1(-3.325,-10.525)
  Bottom Layer w0.3: v1(-3.325,-10.525) -2.8,-11.05 P11.13@-2.8,-12
UART_3V3_RX: D12.1 P4.10 R28.1 | length 15.7
  Top Layer w0.15: v2(4.125,-0.475) 4.125,-0.7 3.55,-1.275 3.55,-2.275 4.225,-2.95 6.243,-2.95 6.5,-3.25 P4.10@6.5,-4.3 6.5,-5.275 D12.1@6.275,-5.5
  Mid-Layer 1 w0.15: v2(4.125,-0.475) 4.125,-0.025 v3(4.65,0.5)
  Mid-Layer 6 w0.15: v1(2.625,4.35) 2.675,4.4 3.23,4.4 3.45,4.18 3.45,3.93 4.725,2.655 4.725,0.575 v3(4.65,0.5)
  Bottom Layer w0.15: v1@2.6,4.462 2.6,5.9 R28.1@2.7,6
UART_3V3_TX: D11.6 P4.12 R26.1 | length 14.9
  Top Layer w0.15: D11.6@5.419,-5.5 5.5,-5.419 P4.12@5.5,-4.3 v2(5.5,-3.325)
  Mid-Layer 1 w0.15: v2(5.5,-3.325) 6.275,-3.325 v3(6.438,-3.162)
  Mid-Layer 6 w0.15: v1(4.75,3.825) 5.549,3.026 5.549,2.231 7.275,0.505 7.275,-0.425 8,-1.15 8,-1.592 7.692,-1.9 7.675,-1.9 v3@6.425,-3.15
  Bottom Layer w0.15: R26.1@3.575,6 3.575,5.929 4.75,4.754 v1(4.75,3.825)
UART_COCO_RX: P10.49 R28.2 | length 2.2
  Bottom Layer w0.2: P10.49@1.75,8.4 1.75,7.268 2.018,7 R28.2@2.7,7
UART_COCO_TX: P10.51 R26.2 | length 2.3
  Mid-Layer 6 w0.2: v1(2.25,7.5) 2.825,6.925 v1(3.425,6.925)
  Bottom Layer w0.3: v1(2.25,7.5) P10.51@2.25,8.4
pads on no net: BRK1.0 BRK2.0 BRK3.0 BRK4.0 D3.2 D3.4 D3.6 D3.8 D3.10 D8.2 D8.4 D8.6 D8.8 D8.10 FD1.1 FD2.1 FD3.1 FD4.1 FD5.1 FD6.1 FD7.1 FD8.1 FD9.1 FD10.1 ORIGIN1.1 P4.7 P4.S1 P10.3 P10.21 P10.22 P10.23 P10.26 P10.27 P10.37 P10.39 P10.40 P10.42 P10.43 P10.44 P10.45 P10.47 P10.48 P10.50 P10.52 P10.53 P10.54 P10.56 P10.61 P10.62 P10.H1 P10.H2 P11.3 P11.35 P11.37 P11.39 P11.41 P11.43 P11.45 P11.H1 P11.H2 U1.C1 U4.1 U12. U13.1 U13.5 U15.C1

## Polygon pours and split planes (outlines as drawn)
GND_D on Mid-Layer 1 "GND_D_L02_P037" (solid, remove dead copper, pour order 37): -4.604,-6.72 -4.604,-6.172 -7.551,-6.172 -7.551,-5.155 -7.551,0.776 -10.14,3.365 -10.14,6.84 -12.25,8.95 -12.25,12.549 -14.2,14.499 -14.2,15.725 12.955,15.725 12.955,8.055 12.7,7.8 12.381,7.8 12,7.419 12,6.845 11.325,6.17 11.325,2.482 10.693,1.85 8.865,1.85 8.865,1.832 8.31,1.278 8.31,0.501 8.761,0.05 10.855,0.05 10.855,0.065 11.404,0.613 12.955,0.613 12.955,-14.498 -3.3,-14.498 -3.3,-8.024
5V_DCDC on Mid-Layer 1 "5V_DCDC_L02_P178" (solid, pour order 178): -4.813,-6.615 -4.813,-6.257 -6.535,-6.257 -6.535,-10.575 -4.718,-10.575 ccw(c-4.718,-10.03) -4.173,-10.03 -4.173,-7.871 ccw(c-5.256,-7.871) -4.49,-7.105 -4.689,-6.906 cw(c-4.396,-6.614) -4.81,-6.614
GND_DCDC on Mid-Layer 1 "GND_DCDC_L02_P172" (solid, pour order 172): -6.49,-5.523 -6.49,-7.45 -6.75,-7.45 -6.75,-9.51 -6.95,-9.71 -6.95,-10.82 -7.5,-11.37 -7.5,-11.221 -9.046,-9.675 -9.65,-9.071 -9.65,-6.364 -8.814,-5.523
NetC44_1 on Mid-Layer 1 "NONET_L-01_P-001" (solid, pour order 80): -7.532,-12.348 cw(c-8.186,-11.877) -8.186,-12.683 cw(c-8.186,-12.344) -8.454,-12.552 ccw(c-8.899,-12.898) -8.501,-12.499 -8.925,-12.075 ccw(c-9.981,-13.13) -9.981,-11.638 -11.305,-11.416 -11.42,-10.163 -11.73,-9.654 -12.856,-8.983 -13.1,-8.6 cw(c-12.577,-8.351) -12.825,-7.828 -10.509,-7.828 cw(c-10.508,-8.355) -9.981,-8.355 -9.981,-8.963 ccw(c-8.84,-8.907) -9.607,-9.754 -7.825,-11.537 ccw(c-6.331,-10.043) -7.624,-11.714 cw(c-7.906,-12.078)
NetC11_2 on Mid-Layer 1 "NETC11_2_L02_P029" (solid, remove dead copper, pour order 29): 3.429,7.946 0.812,10.562 0.813,11.971 1.404,11.971 1.6,11.775 2.314,11.775 2.6,12.061 2.6,14.325 5.4,14.325 5.4,12.449 5.709,12.14 6.908,12.14 7.658,12.89 9.16,12.89 9.575,12.475 9.575,9.025 8.15,7.6 6.75,7.6 6.579,7.771 3.604,7.771
NetC3_2 on Mid-Layer 1 "NETC3_2_L02_P025" (solid, remove dead copper, pour order 25): -1.92,8.53 -2.675,7.775 -9.38,7.775 -9.38,11.32 -8.825,11.875 -7.325,11.875 -7.06,12.14 -5.94,12.14 -5.575,12.505 -5.575,14.07 -2.5,14.075 -2.5,12.42 -1.92,11.84
+V_BUS on Mid-Layer 1 "+V_BUS_L02_P013" (solid, remove dead copper, pour order 13): -7.75,-2.954 -12.069,-2.954 -14.855,-5.73 -14.91,-5.785 -14.91,-7.959 -20.775,-7.959 -20.775,8.6 -12.483,8.6 -9.125,5.242 -9.125,1.964 -7.737,0.576 -7.75,0.564
+LOGIC_DCDC on Mid-Layer 1 "NONET_L-01_P-001" (solid, pour order 82): -8.859,-12.547 -8.859,-14.04 cw(c-9.064,-14.04) -9.064,-14.244 cw(c-9.144,-13.688) -9.144,-14.25 -11.413,-14.25 cw(c-11.413,-13.863) -11.8,-13.863 -11.8,-13.626 ccw(c-12.056,-13.626) -11.875,-13.445 -11.922,-13.398 cw(c-11.674,-13.15) -12.025,-13.15 -12.025,-12.941 cw(c-11.684,-12.941) -11.925,-12.7 cw(c-11.321,-13.304) -11.321,-12.45 -11.1,-12.45 ccw(c-11.1,-11.743) -10.6,-12.243 -10.45,-12.093 cw(c-10.054,-12.489) -10.054,-11.929 -10,-11.929 cw(c-10,-13.193) -9.107,-12.299
PE1 on Top Layer "PE1_L01_P019" (solid, remove dead copper, pour order 19): -8.719,12.018 ccw(c-8.719,11.065) -9.671,11.065 cw(c-12.237,11.065) -12.237,8.5 -14.175,8.517 -15.185,8.517 cw(c-15.185,11.082) -17.75,11.082 -17.75,12.71 cw(c-15.185,12.71) -15.185,15.275 -5.875,15.275 -5.875,13.025 cw(c-6.525,13.025) -6.525,12.375 -6.923,12.375 ccw(c-6.923,11.948) -7.225,12.25 cw(c-7.785,12.81) -7.785,12.018
PE on Top Layer "PE_L01_P017" (solid, remove dead copper, pour order 17): 11.634,8.334 cw(c11.434,8.534) 11.432,8.251 10.023,8.259 ccw(c10.019,7.687) 9.662,8.133 ccw(c10.688,6.854) 9.529,8.015 cw(c9.212,8.396) 9.211,7.9 7.703,7.9 cw(c7.703,8.103) 7.5,8.103 7.5,8.375 8.223,8.375 ccw(c8.223,10.915) 10.019,9.119 10.225,9.325 ccw(c9.018,10.532) 10.725,10.532 10.725,11.25 10.725,11.61 ccw(c9.185,11.61) 9.185,13.15 7.82,13.15 ccw(c7.82,12.136) 7.103,12.853 6.708,12.458 6.15,12.458 cw(c6.15,12.908) 5.7,12.908 5.7,14.825 15.4,14.825 15.4,14.65 17.475,12.575 ccw(c19.587,12.575) 18.094,11.081 18.85,10.325 20.087,10.325 20.087,6.775 19.9,6.775 18.475,6.775 18.337,6.912 cw(c18.337,7.439) 17.965,7.067 16.67,8.362 ccw(c16.35,8.042) 16.35,8.494 12.022,8.494 ccw(c12.022,7.945)
NetC44_1 on Top Layer "NONET_L-01_P-001" (solid, pour order 74): -11.303,-11.417 ccw(c-11.195,-11.417) -11.195,-11.525 -9.575,-11.525 cw(c-9.575,-12.025) -9.075,-12.025 -9.075,-13.85 ccw(c-8.7,-13.85) -8.7,-14.225 -7.975,-14.225 ccw(c-7.975,-13.2) -6.95,-13.2 -6.95,-12.731 ccw(c-7.749,-12.731) -7.184,-12.166 -8.564,-10.786 cw(c-7.192,-9.171) -9.304,-9.343 -9.304,-9 ccw(c-10.495,-8.89) -9.575,-8.125 -9.725,-7.925 ccw(c-10.05,-8.197) -10.013,-7.775 -12.706,-7.775 ccw(c-12.706,-8.201) -13.007,-7.9 ccw(c-12.844,-8.063) -13.075,-8.063 -13.075,-8.382 ccw(c-12.307,-8.382) -12.85,-8.925 -12.701,-9.074 cw(c-13.426,-9.8) -12.4,-9.8 ccw(c-12.038,-9.8) -12.294,-10.056 -12.2,-10.15 ccw(c-11.898,-9.848) -11.898,-10.275 -11.666,-10.275 cw(c-11.666,-10.616) -11.425,-10.375 cw(c-11.666,-10.616) -11.325,-10.616 -11.325,-11.364 ccw(c-11.25,-11.364)
GND_D on Top Layer "GND_D_L01_P061" (solid, remove dead copper, pour order 61): 8.032,0.066 -5.15,0.066 -5.15,-3.275 8.044,-3.275
GND_D on Top Layer "GND_D_L01_P059" (solid, remove dead copper, pour order 59): 9.898,-8.603 -0.25,-8.603 -0.25,-12.263 9.912,-12.263
5V_DCDC on Top Layer "NONET_L-01_P-001" (solid, pour order 75): -6.175,-6.372 -4.88,-6.372 -4.775,-6.475 -4.775,-6.65 ccw(c-4.517,-6.65) -4.7,-6.832 -3.657,-7.875 cw(c-4.095,-8.314) -3.475,-8.314 -3.475,-9.448 cw(c-4.052,-9.448) -4.052,-10.025 -7.874,-10.025 cw(c-7.874,-9.524) -8.375,-9.524 -8.375,-8.475 cw(c-7.65,-8.475) -7.65,-7.75 -6.642,-7.75 ccw(c-6.642,-7.283) -6.175,-7.283
5V_DCDC on Top Layer "5V_DCDC_L01_P180" (solid, pour order 180): -8.375,-9.624 -8.375,-9.997 ccw(c-7.785,-9.997) -7.785,-10.587 -4.955,-10.587 ccw(c-5.013,-8.894) -3.775,-10.05 ccw(c-4.268,-9.426) -3.478,-9.339 -7.688,-9.339 ccw(c-7.688,-10.31)
GND_D on Mid-Layer 6 "GND_D_L07_P043" (solid, remove dead copper, pour order 43): -6,-15 -6,-8.263 -4.838,-7.101 -4.838,-5.669 -6.45,-4.058 -7.424,-4.058 -8.579,-2.903 -8.579,5.511 -9.004,5.936 -9.558,5.936 -12.475,8.852 -12.475,12.774 -13.583,13.882 -13.583,15 13.325,15 13.325,7.356 12.844,6.875 12.075,6.875 12.075,6.781 10.444,5.15 10.369,5.225 7.24,5.225 6.875,4.86 6.875,1.648 8.923,-0.4 10.073,-0.4 10.425,-0.048 10.425,0.9 10.622,1.097 13.325,1.097 13.325,-15
GND_DCDC on Mid-Layer 6 "GND_DCDC_L07_P066" (solid, remove dead copper, pour order 66): -7.871,-11.426 -7.871,-8.401 -8.272,-8 -9.574,-8 -9.875,-8.301 -9.875,-11.426 -21,-11.426 -21,-0.6 -17.8,-0.6 -16.047,0.1 -13.213,0.125 -12.875,0.463 -11.349,0.418 -10.968,0.8 -8.35,0.8 -7.95,0.4 -7.95,-4.177 -6.9,-5.227 -5.473,-5.227 -4.818,-5.882 -4.818,-7.018 -6.351,-8.551 -6.351,-10.875 -6.351,-12.875 -7.856,-12.875 -7.856,-14.5 -8.65,-14.5 -8.65,-12.676 -7.856,-11.882 -7.856,-11.426
GND_A on Mid-Layer 6 "GND_A_L07_P027" (solid, remove dead copper, pour order 27): -0.032,-0.05 0.75,-0.832 0.75,-5.4 -1.25,-7.4 -1.25,-9.35 -2.338,-10.438 -5.601,-10.438 -6.175,-9.864 -6.175,-8.075 -5.725,-7.625 -5,-7.625 -4.5,-7.125 -4.5,-4.325 -5,-3.825 -5,-0.725 -4.325,-0.05
STO_RET on Mid-Layer 6 "STO_RET_L07_P063" (solid, remove dead copper, pour order 63): 8.432,-0.2 8.147,0.085 8.145,0.855 7.3,1.7 7.3,2.4 7.1,2.6 7.1,4.7 7.4,5 9.3,5 10,4.3 10.6,4.3 11,4.7 11,5.4 11.5,5.9 12.518,6.918 13.618,6.918 14.2,7.5 15.8,7.5 16.3,7 16.3,4.8 15.9,4.4 13.2,4.4 12.1,3.3 12.1,1.6 11.8,1.3 10.6,1.3 10.2,0.9 10.2,0.1 9.9,-0.2
GND_DCDC on Mid-Layer 6 "GND_DCDC_L07_P186" (solid, pour order 186): -10.127,-12.725 -9.767,-12.365 -9.767,-6.9 -10.325,-6.9 -10.325,-10.204 -10.961,-10.84 -12.136,-10.84 ccw(c-12.136,-11.444) -12.741,-11.445 -12.741,-12.434 ccw(c-12.45,-12.434) -12.45,-12.725
+LOGIC_DCDC on Mid-Layer 6 "+LOGIC_DCDC_L07_P065" (solid, pour order 65): -10.161,-12.764 -10.929,-12.764 ccw(c-10.929,-13.535) -11.7,-13.535 -11.7,-14.105 ccw(c-11.505,-14.105) -11.505,-14.3 -8.978,-14.3 ccw(c-8.978,-14.118) -8.796,-14.118 -8.796,-12.634 -8.221,-12.077 ccw(c-8.591,-11.696) -8.06,-11.696 -8.06,-8.265 ccw(c-8.325,-8.265) -8.325,-8 -9.441,-8 ccw(c-9.441,-8.32) -9.762,-8.32 -9.762,-9.048 -9.762,-12.36 cw(c-10.163,-12.362)
GND_DCDC on Bottom Layer "GND_DCDC_L08_P170" (solid, pour order 170): -8.643,-11.425 ccw(c-8.643,-10.632) -7.85,-10.632 -7.85,-10.05 -6.575,-10.05 -6.575,-12 cw(c-7.1,-12) -7.1,-12.525 -8.65,-12.525
GND_DCDC on Bottom Layer "NONET_L-01_P-001" (solid, pour order 83): -10.711,-9.525 -11.4,-9.525 ccw(c-11.4,-9.825) -11.7,-9.825 -11.7,-12.7 ccw(c-11.625,-12.7) -11.625,-12.775 -11.331,-12.775 ccw(c-11.331,-12.519) -11.15,-12.7 cw(c-10.728,-13.122) -10.728,-12.525 -9.675,-12.525 -9.675,-11.675 -10.711,-11.675
GND_DCDC on Bottom Layer "NONET_L-01_P-001" (solid, pour order 73): -10.442,-9.525 cw(c-10.442,-9.825) -10.142,-9.825 -10.142,-10.883 ccw(c-9.6,-10.883) -9.6,-11.425 -7.685,-11.425 cw(c-7.685,-11.725) -7.385,-11.725 -7.385,-12.229 cw(c-7.668,-12.242) -7.656,-12.525 -11.422,-12.525 cw(c-11.423,-12.248) -11.7,-12.247 -11.7,-11.703 cw(c-11.422,-11.703) -11.422,-11.425 ccw(c-11.422,-11.253) -11.25,-11.253 -11.25,-9.796 cw(c-10.979,-9.796) -10.979,-9.525
no net on Mechanical 16 "NONET_L-01_P-001" (none): -18.073,-15.751 ccw(c-17.225,-14.902) -18.073,-15.752 ccw(c-17.223,-14.904) -18.072,-15.752 cw(c-17.225,-14.902) -18.073,-15.752 cw(c-17.223,-14.904)
no net on Mechanical 16 "NONET_L-01_P-001" (none): -18.073,15.748 cw(c-17.224,14.899) -18.073,15.749 cw(c-17.223,14.901) -18.072,15.749 ccw(c-17.224,14.899) -18.073,15.749 ccw(c-17.223,14.901)
no net on Mechanical 16 "NONET_L-01_P-001" (none): 18.073,-15.748 cw(c17.224,-14.899) 18.073,-15.749 cw(c17.223,-14.901) 18.072,-15.749 ccw(c17.224,-14.899) 18.073,-15.749 ccw(c17.223,-14.901)
no net on Mechanical 16 "NONET_L-01_P-001" (none): 18.073,15.751 ccw(c17.225,14.902) 18.073,15.752 ccw(c17.223,14.904) 18.072,15.752 cw(c17.225,14.902) 18.073,15.752 cw(c17.223,14.904)
no net on Mechanical 16 "PANEL" (hatched 45Degree grid 1 track 0.2, remove dead copper): -28.5,-22 -28.5,139 132.5,139 132.5,-22
5V_D on Mid-Layer 4 "5V_D_L05_P055" (solid, remove dead copper, pour order 55): 3.683,-3.367 3.683,0.302 5.456,2.075 7.739,2.075 7.739,2.425 -0.363,2.425 -0.938,3 -3.602,3 -5.951,5.349 -5.951,6.926 -7.65,8.625 -8.25,9.225 -8.404,9.072 -12.025,9.072 -12.025,2.825 -8.098,-1.102 -8.098,-4.779 -7.65,-5.227 -5.473,-5.227 -5.025,-5.675 -5.025,-9.376 -2.873,-11.528 1.775,-6.88 1.775,-5.275
GND_D on Mid-Layer 4 "GND_D_L05_P051" (solid, remove dead copper, pour order 51): -4.75,3.749 -3.601,2.6 7.938,2.6 10.7,5.362 10.7,11.05 9.414,12.336 8.1,12.336 6.031,10.715 -0.659,10.715 -2.637,8.737 -2.637,5.875 -4.012,5.875 -4.75,5.137
3.3V_D on Mid-Layer 4 "3.3V_D_L05_P200" (solid, remove dead copper, pour order 200): 8.132,1.752 4.252,1.752 3.095,0.595 3.088,-3.687 1.475,-5.3 1.475,-8.15 0.4,-9.225 -1.2,-9.225 -1.55,-9.575 -1.55,-10.475 -0.4,-11.6 -0.4,-14.1 0,-14.5 13.028,-14.5 13.028,14.498 -11.325,14.498 -11.325,9.725 -5.26,9.725 -2.385,12.6 10.79,12.6 11.565,11.825 11.565,8.694 10.682,7.811 10.682,6.768 11.55,5.9 11.55,5.17
MAGNETICS_CT on Mid-Layer 4 "MAGNETICS_CT_L05_P053" (solid, remove dead copper, pour order 53): -7.507,11.832 -2.618,11.832 -0.825,13.675 10.584,13.675 11.775,12.484 11.775,7.625 10.76,7.625 10.76,11.65 9.91,12.5 8.4,12.5 7,11.1 6.875,10.975 5.95,10.975 -0.2,10.975 -2.9,8.275 -2.9,5.985 -4.905,5.985 -8.25,9.33 -8.25,11.089
+LOGIC_DCDC on Mid-Layer 4 "+LOGIC_DCDC_L05_P168" (solid, pour order 168): -13.15,-9.93 -13.15,-14.5 -7.775,-14.5 -7.775,-12.225 -7.775,-9.926
+LOGIC_DCDC on Mid-Layer 4 "+LOGIC_DCDC_L05_P070" (solid, remove dead copper, pour order 70): -21,-0.6 -17.8,-0.6 -16.047,0.1 -13.213,0.125 -12.875,0.463 -11.349,0.418 -10.968,0.8 -8.35,0.8 -7.95,0.4 -7.95,-4.177 -7.775,-4.352 -7.775,-10.843 -21,-10.843
GND_D on Mid-Layer 2 "GND_D_L03_P039" (solid, remove dead copper, pour order 39): -7.549,-4.435 -6.774,-5.209 -5.741,-5.209 -4.603,-6.347 -4.603,-6.716 -3.17,-8.149 -3.17,-15 13,-15 13,0.675 11.48,0.675 10.805,0 8.825,0 8.25,0.575 8.25,1.235 8.965,1.95 10.1,1.95 11.335,3.185 11.335,6.51 12.25,7.425 13,8.175 13,15 -13.85,15 -13.85,14.1 -12.325,12.575 -12.325,8.155 -10.068,5.899 -10.068,3.204 -7.549,0.684
GND_DCDC on Mid-Layer 2 "GND_DCDC_L03_P198" (solid, pour order 198): -21,-0.6 -17.825,-0.6 -16.047,0.1 -13.213,0.125 -12.875,0.463 -11.531,0.463 -10.325,1.5 -8.637,1.5 -7.575,0.437 -7.575,-4.536 -6.884,-5.227 -4.604,-5.283 -4.604,-8.609 -7.012,-11.017 -7.429,-11.013 -9.124,-9.161 -13.411,-9.161 -15.25,-11 -19.425,-11 -21,-9.425
STO_RET on Mid-Layer 2 "STO_RET_L03_P067" (solid, remove dead copper, pour order 67): 11.8,4.7 11.6,4.5 11.6,3 10.225,1.625 8.925,1.625 8.5,1.2 8.5,0.8 9.05,0.25 10.641,0.25 12.284,1.894 12.284,3.745 12.926,4.387 16.076,4.387 16.652,4.963 16.652,7.257 16.109,7.8 13.3,7.8 12.4,6.9 12.4,6.7 11.8,6.1
GND_D on Mid-Layer 5 "GND_D_L06_P057" (solid, remove dead copper, pour order 57): -8.5,1.925 -11.17,1.925 -12.5,3.255 -12.473,7.736 -13.463,8.726 -13.463,15 13,15 13,-15 -6,-15 -6,-10.745 -5.014,-9.759 -5.014,-5.766 -6.39,-4.39 -7.487,-4.39 -8.051,-3.827 -8.051,1.476
GND_DCDC on Mid-Layer 5 "GND_DCDC_L06_P068" (solid, remove dead copper, pour order 68): -6.351,-10.875 -6.351,-14.5 -13.675,-14.5 -13.675,-10.875 -21,-10.875 -21,-0.6 -17.8,-0.6 -16.047,0.1 -13.213,0.125 -12.875,0.463 -11.349,0.418 -10.968,0.8 -8.35,0.8 -7.95,0.4 -7.95,-4.177 -6.9,-5.227 -5.473,-5.227 -5.197,-5.503 -5.197,-9.721
GND_D on Mid-Layer 3 "GND_D_L04_P049" (solid, remove dead copper, pour order 49): -4.675,-7.881 -3.25,-9.306 -3.25,-15 13,-15 13,15 -13.575,15 -13.575,13.874 -12.475,12.774 -12.475,8.521 -10.025,6.071 -10.025,2.845 -8.125,0.945 -8.125,-4.375 -7.273,-5.227 -5.473,-5.227 -4.675,-6.025
GND_DCDC on Mid-Layer 3 "GND_DCDC_L04_P071" (solid, remove dead copper, pour order 71): -3.15,-12.708 -5.158,-12.708 -6.95,-14.5 -7.775,-14.5 -13.21,-14.5 -13.21,-11.005 -21,-11.005 -21,-0.6 -17.8,-0.6 -16.047,0.1 -13.213,0.125 -12.875,0.463 -11.349,0.418 -10.968,0.8 -8.35,0.8 -7.95,0.4 -7.95,-4.177 -6.654,-5.472 -5.228,-5.472 -4.7,-6 -4.7,-8.26 -3.2,-9.76 -3.15,-9.76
